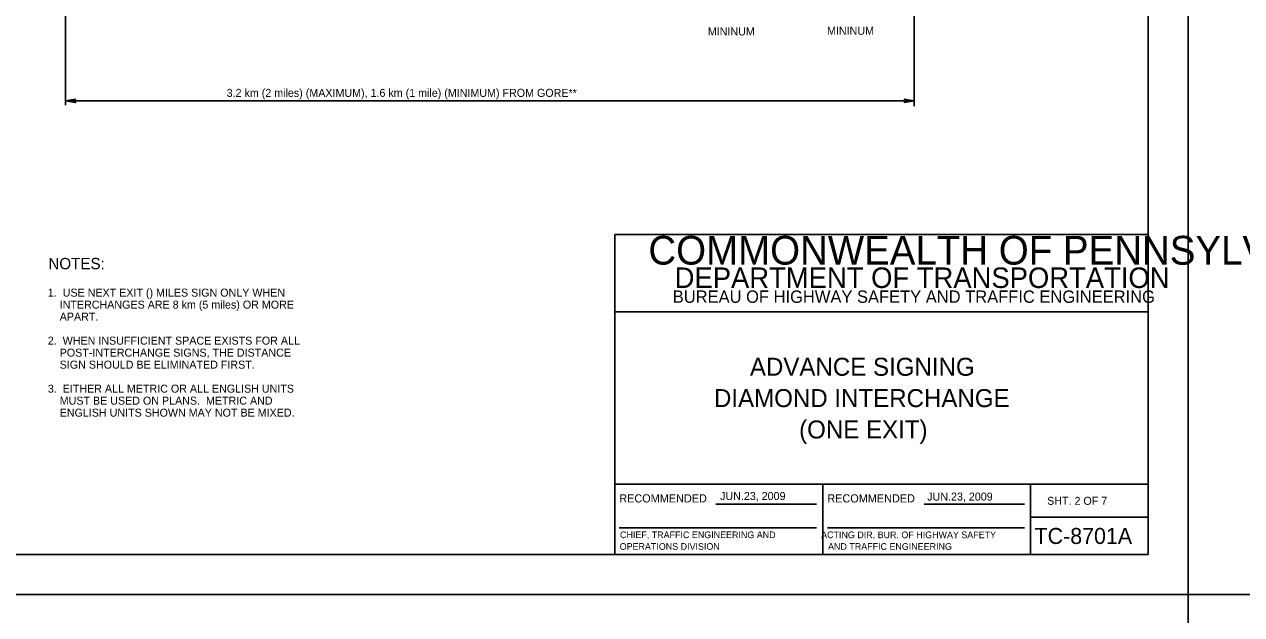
# Model space of a CAD drawing. Extents: x 640994 to 644422, y 298458 to 299646.
# Drawn here: x 642240 to 642696.3, y 299044.1 to 299265.4 of the extents above; entities that cross this region are included whole.
import ezdxf

# ---------------------------------------------------------------- set-up
doc = ezdxf.new("R2010")
doc.units = 0
for name, color, linetype in [('1', 7, 'Continuous'), ('2', 7, 'Continuous'), ('PLT-BNDY', 7, 'Continuous'), ('XCS-GRID-MIN', 7, 'Continuous')]:
    doc.layers.add(name, color=color, linetype=linetype)

msp = doc.modelspace()

# ---------------------------------------------------------------- linework, layer by layer
at = {"layer": '1'}
for p, q in [((642661.31, 299066.63), (642661.31, 299630.63)), ((642461.31, 299066.63), (642461.31, 299186.63)), ((642461.31, 299186.63), (642661.31, 299186.63)), ((642661.31, 299157.63), (642461.31, 299157.63)), ((642461.31, 299093), (642661.31, 299093)), ((642539.31, 299093), (642539.31, 299066.63)), ((642617.19, 299066.63), (642617.19, 299093)), ((642499.24, 299085.57), (642536.87, 299085.57)), ((642577.24, 299085.57), (642614.87, 299085.57)), ((642617.19, 299080.63), (642661.31, 299080.63)), ((642462.99, 299076.68), (642536.87, 299076.68)), ((642540.99, 299076.68), (642614.87, 299076.68)), ((642661.31, 299066.63), (641875.31, 299066.63)), ((641875.31, 299066.63), (642461.31, 299066.63))]:
    msp.add_line(p, q, dxfattribs=at)
at = {"layer": '2'}
for p, q in [((642573.56, 299352.88), (642573.56, 299234.75)), ((642255.44, 299338.75), (642255.44, 299235.13)), ((642573.56, 299236.75), (642255.44, 299236.75))]:
    msp.add_line(p, q, dxfattribs=at)
for points in [[(642258.94, 299236.25), (642258.81, 299236.5), (642255.44, 299236.75), (642258.94, 299236.25), (642259.19, 299236.13), (642255.44, 299236.75), (642258.81, 299236.88), (642258.94, 299237.13), (642255.44, 299236.75), (642259.19, 299237.38), (642258.94, 299237.13)], [(642570.06, 299237.25), (642570.19, 299237), (642573.56, 299236.75), (642570.06, 299237.25), (642569.81, 299237.38), (642573.56, 299236.75), (642570.19, 299236.63), (642570.06, 299236.38), (642573.56, 299236.75), (642569.81, 299236.13), (642570.06, 299236.38)]]:
    msp.add_lwpolyline(points, dxfattribs=at)
at = {"layer": 'XCS-GRID-MIN'}
for points in [[(641835.31, 299645.63), (642676.31, 299645.63), (642676.31, 299051.63), (641835.31, 299051.63)], [(642676.31, 299645.63), (643517.31, 299645.63), (643517.31, 299051.63), (642676.31, 299051.63)], [(641835.31, 299051.63), (642676.31, 299051.63), (642676.31, 298457.63), (641835.31, 298457.63)], [(642676.31, 299051.63), (643517.31, 299051.63), (643517.31, 298457.63), (642676.31, 298457.63)]]:
    msp.add_lwpolyline(points, close=True, dxfattribs=at)

# ---------------------------------------------------------------- texts
at = {"layer": '1'}
for s, height, p in [('COMMONWEALTH OF PENNSYLVANIA', 10.7828, (642473.9, 299175.36)), ('DEPARTMENT OF TRANSPORTATION', 7.6837, (642483.76, 299166.61)), ('BUREAU OF HIGHWAY SAFETY AND TRAFFIC ENGINEERING', 4.6253, (642483.04, 299161.04)), ('ADVANCE SIGNING', 6.75, (642511.96, 299133.69)), ('DIAMOND INTERCHANGE', 6.75, (642498.49, 299121.94)), ('(ONE EXIT)', 6.75, (642530.41, 299110.19)), ('RECOMMENDED', 3.048, (642462.99, 299086.2)), ('RECOMMENDED', 3.048, (642540.99, 299086.2)), ('SHT. 2 OF 7', 3, (642623.4, 299085.31)), ('TC-8701A', 6, (642618.68, 299070.63))]:
    msp.add_text(s, height=height, dxfattribs=at).set_placement(p)
at = {"layer": '2'}
for s, height, p in [(' MININUM', 3, (642495.07, 299261.28)), (' MININUM', 3, (642539.76, 299261.54)), ('3.2 km (2 miles) (MAXIMUM), 1.6 km (1 mile) (MINIMUM) FROM GORE**', 3, (642315.8, 299238.25)), ('NOTES:', 4.25, (642248.97, 299173.63)), ('1.  USE NEXT EXIT () MILES SIGN ONLY WHEN', 3, (642248.75, 299163.36)), ('    INTERCHANGES ARE 8 km (5 miles) OR MORE', 3, (642248.75, 299158.86)), ('    APART.', 3, (642248.75, 299154.36)), ('2.  WHEN INSUFFICIENT SPACE EXISTS FOR ALL', 3, (642248.75, 299145.36)), ('    POST-INTERCHANGE SIGNS, THE DISTANCE', 3, (642248.75, 299140.86)), ('    SIGN SHOULD BE ELIMINATED FIRST.', 3, (642248.75, 299136.36)), ('3.  EITHER ALL METRIC OR ALL ENGLISH UNITS', 3, (642248.75, 299127.36)), ('    MUST BE USED ON PLANS.  METRIC AND', 3, (642248.75, 299122.86)), ('    ENGLISH UNITS SHOWN MAY NOT BE MIXED.', 3, (642248.75, 299118.36)), ('JUN.23, 2009', 3, (642500.78, 299087.1)), ('JUN.23, 2009', 3, (642578.44, 299086.89))]:
    msp.add_text(s, height=height, dxfattribs=at).set_placement(p)
at = {"layer": 'PLT-BNDY'}
for s, p in [('CHIEF, TRAFFIC ENGINEERING AND', (642463.28, 299072.81)), ('  ACTING DIR. BUR. OF HIGHWAY SAFETY', (642536.81, 299072.8)), ('  ACTING DIR. BUR. OF HIGHWAY SAFETY', (642536.81, 299072.8)), ('OPERATIONS DIVISION', (642463.14, 299068.44))]:
    msp.add_text(s, height=2.5, dxfattribs=at).set_placement(p)
msp.add_text('AND TRAFFIC ENGINEERING', height=2.5, rotation=360, dxfattribs=at).set_placement((642541.25, 299068.43))
msp.add_text('AND TRAFFIC ENGINEERING', height=2.5, rotation=360, dxfattribs=at).set_placement((642541.25, 299068.43))

doc.saveas('drawing.dxf')
